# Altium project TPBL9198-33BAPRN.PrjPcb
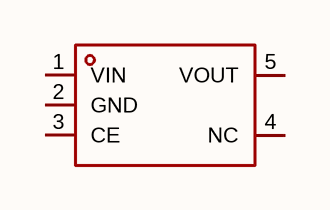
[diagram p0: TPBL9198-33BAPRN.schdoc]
1 sheet, 1 parts. Net scope: global (net labels, ports and power ports of the same name join across sheets).

## Sheet TPBL9198-33BAPRN.schdoc
size 127 x 101 mm

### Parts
U?  tpbl9198-33baprn  [SOT-23-5_L2.9-W1.6-P0.95-LS2.8-BR]  (value not drawn)

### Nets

Not connected (* = marked no-connect by the designer): U? 1(VIN) 2(GND) 3(CE) 4(NC) 5(VOUT)

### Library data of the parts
U? = tpbl9198-33baprn: 输出极性:正极;工作电压:6V;输出电压:3.3V;输出电流:300mA;电源纹波抑制比(PSRR):70dB@(1kHz);输出类型:固定;; Manufacturer: TECH PUBLIC(台舟); AddInBom: yes; ModelId: 7ba65df16e7b4570af156e925f9c37fe; ModelTransform: 114.173,114.173,0,90,0,0,0,0,0; Output Configuration: 正极; Voltage - Supply: 6V; Output Voltage: 3.3V; Output Current: 300mA; Voltage Dropout: 90mV@(100mA)；230mV@(200mA); standby current: 70uA; Noise: 50uVrms; Output Type: 固定; Number of Outputs: 1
